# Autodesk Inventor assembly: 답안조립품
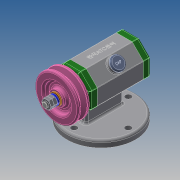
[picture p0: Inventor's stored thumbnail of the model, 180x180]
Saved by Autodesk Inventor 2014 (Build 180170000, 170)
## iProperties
Created: 2021-02
Part Number: 답안조립품
Document SubType Name: Assembly
Designer: kb542-20
Author: kb542-20
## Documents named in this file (14)
- C:\Users\kb542-20\Desktop\710204V1017\답안조립품.iam
- C:\Users\kb542-20\Desktop\710204V1017\V벨트풀리.ipt
- C:\Users\kb542-20\Desktop\710204V1017\고무캡.ipt
- C:\Users\kb542-20\Desktop\710204V1017\너트 M8.ipt
- C:\Users\kb542-20\Desktop\710204V1017\뒤커버.ipt
- C:\Users\kb542-20\Desktop\710204V1017\베어링 15 x 32 x 9.ipt
- C:\Users\kb542-20\Desktop\710204V1017\본체.ipt
- C:\Users\kb542-20\Desktop\710204V1017\볼트 M4 x 12.ipt
- C:\Users\kb542-20\Desktop\710204V1017\스프링와셔 8.ipt
- C:\Users\kb542-20\Desktop\710204V1017\앞커버.ipt
- C:\Users\kb542-20\Desktop\710204V1017\오일 실 15 25 7.ipt
- C:\Users\kb542-20\Desktop\710204V1017\와셔 8x17.ipt
- C:\Users\kb542-20\Desktop\710204V1017\축.ipt
- C:\Users\kb542-20\Desktop\710204V1017\키 3 x 3 x 12.ipt
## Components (2 placed, 2 different names)
1. V벨트풀리:1 — 각도:1
2. 고무캡:1
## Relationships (1: Angle 1)
- 각도:1 [Angle]: V벨트풀리:1
